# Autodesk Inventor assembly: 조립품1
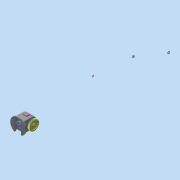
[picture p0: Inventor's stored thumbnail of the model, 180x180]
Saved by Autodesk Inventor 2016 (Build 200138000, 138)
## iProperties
Created: 2024-08
Part Number: 조립품1
Material: 일반
Document SubType Name: Assembly
Designer: pc-2
Author: pc-2
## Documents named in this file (21)
- C:\Users\pc-2\Desktop\740804V1018\조립품1.iam
- C:\Users\pc-2\Desktop\740804V1018\1.ipt
- C:\Users\pc-2\Documents\Inventor\깊은 홈 볼 베어링 6904.ipt
- C:\Users\pc-2\Desktop\740804V1018\가져온 구성요소\뒷커버\뒷커버.ipt
- C:\Users\pc-2\Desktop\740804V1018\가져온 구성요소\링크\링크.ipt
- C:\Users\pc-2\Desktop\740804V1018\가져온 구성요소\부시 커버\부시 커버.ipt
- C:\Users\pc-2\Desktop\740804V1018\가져온 구성요소\스퍼 기어\스퍼 기어.ipt
- C:\Users\pc-2\Desktop\740804V1018\가져온 구성요소\스프링 와셔 M10\스프링 와셔 M10.ipt
- C:\Users\pc-2\Desktop\740804V1018\가져온 구성요소\앞커버\앞커버.ipt
- C:\Users\pc-2\Desktop\740804V1018\가져온 구성요소\오일레스 부시 20 15\오일레스 부시 20 15.ipt
- C:\Users\pc-2\Desktop\740804V1018\가져온 구성요소\오일실 20 32 5\오일실 20 32 5.ipt
- C:\Users\pc-2\Desktop\740804V1018\가져온 구성요소\윗커버\윗커버.ipt
- C:\Users\pc-2\Desktop\740804V1018\가져온 구성요소\육각 너트 M10x1\육각 너트 M10x1.ipt
- C:\Users\pc-2\Desktop\740804V1018\가져온 구성요소\육각 소켓 머리 볼트 M4x10\육각 소켓 머리 볼트 M4x10.ipt
- C:\Users\pc-2\Desktop\740804V1018\가져온 구성요소\칼라\칼라.ipt
- C:\Users\pc-2\Desktop\740804V1018\가져온 구성요소\펀치\펀치.ipt
- C:\Users\pc-2\Desktop\740804V1018\가져온 구성요소\편심축\편심축.ipt
- C:\Users\pc-2\Desktop\740804V1018\가져온 구성요소\평와셔 M10\평와셔 M10.ipt
- C:\Users\pc-2\Desktop\740804V1018\가져온 구성요소\평행키 5x5x12\평행키 5x5x12.ipt
- C:\Users\pc-2\Desktop\740804V1018\가져온 구성요소\핀\핀.ipt
- C:\Users\pc-2\Desktop\740804V1018\가져온 구성요소\E형 멈춤링 10-8\E형 멈춤링 10-8.ipt
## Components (3 placed, 3 different names)
1. 1:1 — 각도:1
2. 핀:1
3. E형 멈춤링 10-8:1
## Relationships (1: Angle 1)
- 각도:1 [Angle]: 1:1
